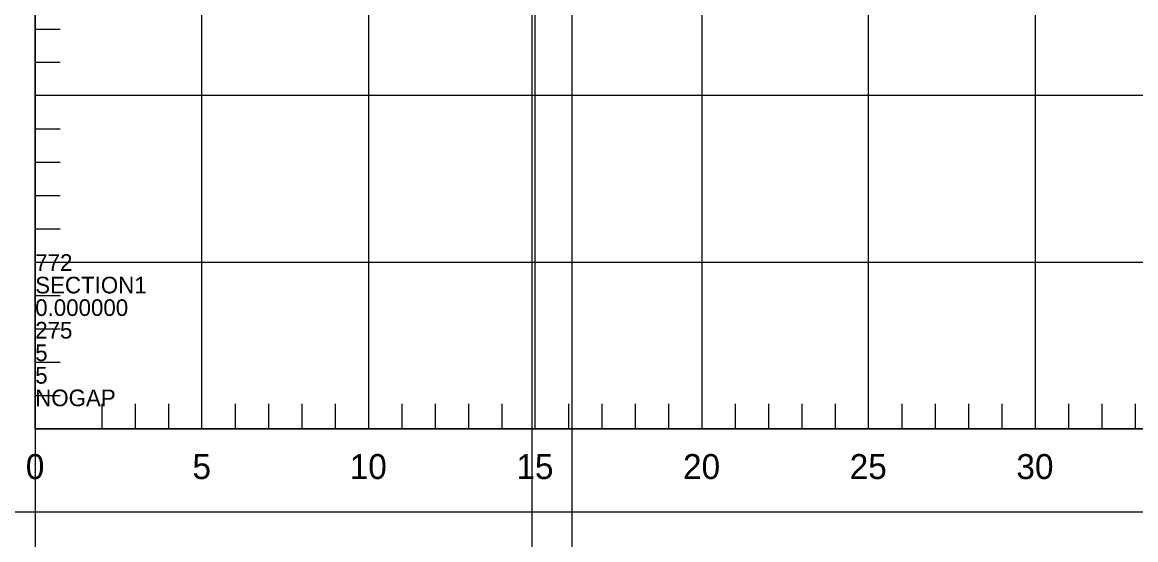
# Model space of a CAD drawing. Extents: x 1578769 to 1579225, y 724002 to 724828.
# Drawn here: x 1578824.75 to 1578858.15, y 724248.81 to 724264.34 of the extents above; entities that cross this region are included whole.
import ezdxf

# ---------------------------------------------------------------- set-up
doc = ezdxf.new("R2010")
doc.units = 0
for name, color, linetype in [('1', 7, 'Continuous'), ('Default', 7, 'Continuous'), ('Old_Level_1', 7, 'Continuous'), ('Old_Level_41', 7, 'Continuous'), ('Old_Level_42', 7, 'Continuous')]:
    doc.layers.add(name, color=color, linetype=linetype)

msp = doc.modelspace()

# ---------------------------------------------------------------- linework, layer by layer
at = {"layer": 'Default'}
for p, q in [((1578825.136, 724252.141), (1578825.136, 724502.141)), ((1578841.23, 724437.474), (1578841.23, 724187.474)), ((1578840.032, 724387.146), (1578840.032, 724137.146)), ((1578825.136, 724252.141), (1579225.136, 724252.141)), ((1578825.136, 724252.141), (1578825.136, 724002.141))]:
    msp.add_line(p, q, dxfattribs=at)
at = {"layer": 'Old_Level_1'}
for points in [[(1578820.135, 724284.641), (1578927.635, 724284.641), (1578927.635, 724249.641), (1578820.135, 724249.641)], [(1578825.135, 724282.141), (1578925.135, 724282.141), (1578925.135, 724252.141), (1578825.135, 724252.141)]]:
    msp.add_lwpolyline(points, close=True, dxfattribs=at)
at = {"layer": 'Old_Level_41'}
for p, q in [((1578830.135, 724252.141), (1578830.135, 724282.141)), ((1578835.135, 724282.141), (1578835.135, 724252.141)), ((1578840.135, 724252.141), (1578840.135, 724282.141)), ((1578845.135, 724282.141), (1578845.135, 724252.141)), ((1578850.135, 724252.141), (1578850.135, 724282.141)), ((1578855.135, 724282.141), (1578855.135, 724252.141)), ((1578825.135, 724279.641), (1578825.135, 724252.141))]:
    msp.add_line(p, q, dxfattribs=at)
for points in [[(1578925.135, 724262.141), (1578825.135, 724262.141)], [(1578825.135, 724257.141), (1578925.135, 724257.141)]]:
    msp.add_lwpolyline(points, dxfattribs=at)
at = {"layer": 'Old_Level_42'}
for p, q in [((1578825.135, 724264.141), (1578825.885, 724264.141)), ((1578825.135, 724263.141), (1578825.885, 724263.141)), ((1578825.135, 724261.141), (1578825.885, 724261.141)), ((1578825.135, 724260.141), (1578825.885, 724260.141)), ((1578825.135, 724259.141), (1578825.885, 724259.141)), ((1578825.135, 724258.141), (1578825.885, 724258.141)), ((1578825.135, 724256.141), (1578825.885, 724256.141)), ((1578825.135, 724255.141), (1578825.885, 724255.141)), ((1578825.135, 724254.141), (1578825.885, 724254.141)), ((1578825.135, 724253.141), (1578825.885, 724253.141)), ((1578827.135, 724252.891), (1578827.135, 724252.141)), ((1578828.135, 724252.891), (1578828.135, 724252.141)), ((1578829.135, 724252.891), (1578829.135, 724252.141)), ((1578831.135, 724252.891), (1578831.135, 724252.141)), ((1578832.135, 724252.891), (1578832.135, 724252.141)), ((1578833.135, 724252.891), (1578833.135, 724252.141)), ((1578834.135, 724252.891), (1578834.135, 724252.141)), ((1578836.135, 724252.891), (1578836.135, 724252.141)), ((1578837.135, 724252.891), (1578837.135, 724252.141)), ((1578838.135, 724252.891), (1578838.135, 724252.141)), ((1578839.135, 724252.891), (1578839.135, 724252.141)), ((1578841.135, 724252.891), (1578841.135, 724252.141)), ((1578842.135, 724252.891), (1578842.135, 724252.141)), ((1578843.135, 724252.891), (1578843.135, 724252.141)), ((1578844.135, 724252.891), (1578844.135, 724252.141)), ((1578846.135, 724252.891), (1578846.135, 724252.141)), ((1578847.135, 724252.891), (1578847.135, 724252.141)), ((1578848.135, 724252.891), (1578848.135, 724252.141)), ((1578849.135, 724252.891), (1578849.135, 724252.141)), ((1578851.135, 724252.891), (1578851.135, 724252.141)), ((1578852.135, 724252.891), (1578852.135, 724252.141)), ((1578853.135, 724252.891), (1578853.135, 724252.141)), ((1578854.135, 724252.891), (1578854.135, 724252.141)), ((1578856.135, 724252.891), (1578856.135, 724252.141)), ((1578857.135, 724252.891), (1578857.135, 724252.141)), ((1578858.135, 724252.891), (1578858.135, 724252.141))]:
    msp.add_line(p, q, dxfattribs=at)

# ---------------------------------------------------------------- texts
at = {"layer": '1'}
for s, p in [('0', (1578824.853, 724250.631)), ('5', (1578829.853, 724250.631)), ('10', (1578834.569, 724250.631)), ('15', (1578839.569, 724250.631)), ('20', (1578844.569, 724250.631)), ('25', (1578849.569, 724250.631)), ('30', (1578854.569, 724250.631))]:
    msp.add_text(s, height=0.75, dxfattribs=at).set_placement(p)
at = {"layer": 'Default'}
for s, p in [('772', (1578825.136, 724256.881)), ('SECTION1', (1578825.136, 724256.204)), ('0.000000', (1578825.136, 724255.527)), ('275', (1578825.136, 724254.849)), ('5', (1578825.136, 724254.172)), ('5', (1578825.136, 724253.495)), ('NOGAP', (1578825.136, 724252.818))]:
    msp.add_text(s, height=0.5, dxfattribs=at).set_placement(p)

doc.saveas('drawing.dxf')
